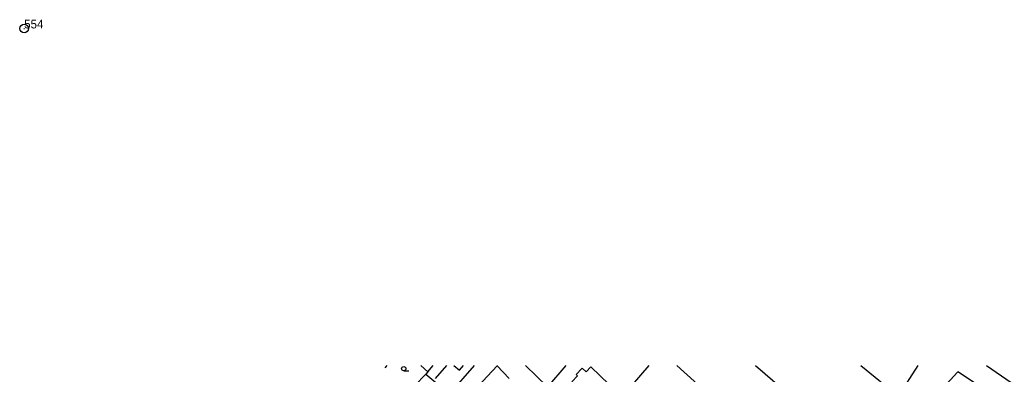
# Model space of a CAD drawing. Extents: x -504997 to -503568, y -1079870 to -1078007.
# Drawn here: x -504726.7 to -504382, y -1078629.2 to -1078505.9 of the extents above; entities that cross this region are included whole.
import ezdxf

# ---------------------------------------------------------------- set-up
doc = ezdxf.new("R2010")
doc.units = 0
for name, color, linetype in [('Hranice parcel', 7, 'Continuous'), ('Vnitřní kresba', 7, 'Continuous'), ('Vrstva 30', 7, 'Continuous'), ('Vrstva 31', 7, 'Continuous'), ('Vrstva 32', 7, 'Continuous'), ('Značky kultur', 7, 'Continuous')]:
    doc.layers.add(name, color=color, linetype=linetype)

msp = doc.modelspace()

# ---------------------------------------------------------------- linework, layer by layer
at = {"layer": 'Hranice parcel'}
for p, q in [((-504599.72, -1078626.96), (-504598.99, -1078626.15)), ((-504587.33, -1078626.15), (-504584.87, -1078628.4)), ((-504583.69, -1078650.73), (-504560.74, -1078626.29)), ((-504560.74, -1078626.29), (-504560.89, -1078626.15)), ((-504556.52, -1078630.76), (-504560.74, -1078626.29)), ((-504550.86, -1078626.15), (-504543.22, -1078633.58)), ((-504536.89, -1078626.15), (-504543.22, -1078633.58)), ((-504508.05, -1078626.15), (-504527.23, -1078648.54)), ((-504498.24, -1078626.15), (-504480.17, -1078642.51)), ((-504470.98, -1078626.15), (-504456.71, -1078638.45)), ((-504434.31, -1078626.15), (-504421.16, -1078636.85)), ((-504421.16, -1078636.85), (-504414.38, -1078626.15)), ((-504594.06, -1078637.92), (-504585.52, -1078629.17)), ((-504584.87, -1078628.4), (-504585.52, -1078629.17))]:
    msp.add_line(p, q, dxfattribs=at)
for points in [[(-504585.52, -1078629.17), (-504582.12, -1078632.17), (-504577.37, -1078636.19), (-504568.57, -1078626.15)], [(-504584.87, -1078628.4), (-504582.98, -1078626.15)], [(-504533.89, -1078632.8), (-504534.81, -1078631.93), (-504532.83, -1078629.85), (-504533.33, -1078629.38), (-504531.17, -1078627.13), (-504529.78, -1078628.45), (-504528.15, -1078626.72), (-504521.75, -1078632.83), (-504528.16, -1078639.59), (-504534.56, -1078633.51), (-504533.89, -1078632.8)], [(-504390.65, -1078626.15), (-504382.03, -1078632.08)], [(-504390.39, -1078656.39), (-504386.93, -1078647.57), (-504385.6, -1078640.48), (-504390.91, -1078634.75), (-504400.58, -1078628.4), (-504408.62, -1078637.13), (-504411.85, -1078640.13)]]:
    msp.add_lwpolyline(points, dxfattribs=at)
at = {"layer": 'Vnitřní kresba'}
for p, q in [((-504582.14, -1078630.76), (-504578.29, -1078626.15)), ((-504575.81, -1078626.15), (-504573.86, -1078627.78)), ((-504573.86, -1078627.78), (-504572.5, -1078626.15))]:
    msp.add_line(p, q, dxfattribs=at)
at = {"layer": 'Vrstva 30'}
msp.add_line((-504725.29, -1078508.91), (-504725.09, -1078508.91), dxfattribs=at)
msp.add_circle((-504725.19, -1078508.91), 1.51, dxfattribs=at)
at = {"layer": 'Vrstva 31'}
msp.add_line((-504725.19, -1078508.91), (-504725.19, -1078508.91), dxfattribs=at)
at = {"layer": 'Značky kultur'}
msp.add_line((-504593.22, -1078628.05), (-504591.47, -1078628.05), dxfattribs=at)
msp.add_circle((-504593.22, -1078627.3), 0.75, dxfattribs=at)

# ---------------------------------------------------------------- texts
at = {"layer": 'Vrstva 32'}
msp.add_text('554', height=3, dxfattribs=at).set_placement((-504725.19, -1078508.91))

doc.saveas('drawing.dxf')
